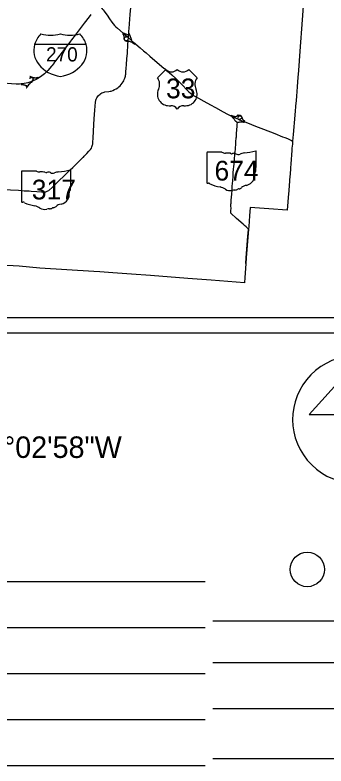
# Model space of a CAD drawing. Extents: x 0 to 34, y 0 to 22.
# Drawn here: x 6.458 to 8.488, y 11.177 to 16.072 of the extents above; entities that cross this region are included whole.
import ezdxf

# ---------------------------------------------------------------- set-up
doc = ezdxf.new("R2010")
doc.units = 0
for name, color, linetype in [('GM_X_County', 7, 'Continuous'), ('GM_X_Interchange_Ramps', 7, 'Continuous'), ('GM_X_Interstate_Route', 7, 'Continuous'), ('GM_X_Interstate_Shield', 7, 'Continuous'), ('GM_X_State_Route', 7, 'Continuous'), ('GM_X_State_Shield', 7, 'Continuous'), ('GM_X_US_Route', 7, 'Continuous'), ('GM_X_US_Shield', 7, 'Continuous'), ('SH_Data', 7, 'Continuous'), ('SH_Text', 7, 'Continuous')]:
    doc.layers.add(name, color=color, linetype=linetype)

msp = doc.modelspace()

# ---------------------------------------------------------------- linework, layer by layer
at = {"layer": 'GM_X_County'}
msp.add_lwpolyline([(8.3489, 16.2792), (8.3313, 16.0413), (8.3161, 15.8364), (8.3076, 15.7102), (8.3077, 15.7078), (8.3044, 15.666), (8.2999, 15.6045), (8.2955, 15.5437), (8.2932, 15.5151), (8.2922, 15.5061), (8.2906, 15.5018), (8.2836, 15.418), (8.2734, 15.2932), (8.2696, 15.2487), (8.2685, 15.2309), (8.267, 15.2168), (8.2657, 15.2028), (8.265, 15.1893), (8.2573, 15.1017), (8.2563, 15.0765), (8.2566, 15.0746), (8.2563, 15.0706), (8.2557, 15.0641), (8.2515, 15.0144), (8.2503, 14.9991), (8.2491, 14.9836), (8.2476, 14.9659), (8.2441, 14.9236), (8.2433, 14.9088), (8.2333, 14.7993), (8.1147, 14.8086), (7.9925, 14.8176), (7.9882, 14.7624), (7.983, 14.6937), (7.9818, 14.6762), (7.9675, 14.4885), (7.9649, 14.4509), (7.9575, 14.3612), (7.9551, 14.3263), (7.7391, 14.3437), (7.5857, 14.3553), (7.3417, 14.3728), (7.219, 14.3818), (7.0969, 14.3902), (7.0112, 14.3967), (6.9733, 14.3992), (6.6207, 14.4227), (6.4853, 14.4341), (6.2434, 14.4473)], dxfattribs=at)
at = {"layer": 'GM_X_Interchange_Ramps'}
for points in [[(7.1631, 15.9534), (7.1604, 15.9504), (7.1623, 15.9478), (7.1634, 15.9461), (7.1644, 15.9441), (7.1651, 15.9426), (7.1658, 15.9409), (7.1665, 15.939), (7.167, 15.9372), (7.1675, 15.9348), (7.1678, 15.9323), (7.1695, 15.9155), (7.1701, 15.9132), (7.1708, 15.9115), (7.1716, 15.9101), (7.1728, 15.9084), (7.1743, 15.9068), (7.1755, 15.9058), (7.177, 15.9047), (7.1785, 15.9039), (7.1798, 15.9034), (7.1816, 15.9028), (7.1832, 15.9026), (7.1854, 15.9022), (7.1942, 15.9014), (7.1961, 15.9012)], [(7.1989, 15.9399), (7.1975, 15.94), (7.1724, 15.9516), (7.1673, 15.9545), (7.1649, 15.9518)], [(7.1967, 15.9088), (7.1942, 15.909), (7.1933, 15.9077), (7.1921, 15.9065), (7.1909, 15.9056), (7.1896, 15.9049), (7.1884, 15.9043), (7.1872, 15.904), (7.1855, 15.9037), (7.1839, 15.9036), (7.1823, 15.9038), (7.1806, 15.9043), (7.1779, 15.9058), (7.176, 15.9071), (7.1744, 15.9086), (7.173, 15.9104), (7.1721, 15.9119), (7.1715, 15.9133), (7.1709, 15.9153), (7.1706, 15.9174), (7.1706, 15.9195), (7.171, 15.9218), (7.1716, 15.9232), (7.1722, 15.9244), (7.1731, 15.9255), (7.1745, 15.9269), (7.1759, 15.9279), (7.1775, 15.9287), (7.1791, 15.9291), (7.1807, 15.9293), (7.1825, 15.9293), (7.1839, 15.929), (7.1851, 15.9286), (7.1867, 15.9279), (7.1895, 15.9308)], [(7.209, 15.9367), (7.2084, 15.9365), (7.2076, 15.9374), (7.2065, 15.9382), (7.2054, 15.9389), (7.2041, 15.9394), (7.2028, 15.9397), (7.202, 15.9398), (7.2011, 15.9398), (7.1989, 15.9399)], [(7.2189, 15.9056), (7.2212, 15.9081), (7.2192, 15.9118), (7.209, 15.9367), (7.2032, 15.9507), (7.2021, 15.9536), (7.1998, 15.9538)], [(7.1961, 15.9012), (7.1977, 15.9011), (7.2023, 15.9008), (7.2038, 15.9006), (7.2056, 15.9003), (7.2105, 15.8992), (7.2144, 15.898), (7.2179, 15.8964), (7.221, 15.8949), (7.2241, 15.893), (7.2401, 15.8823), (7.2427, 15.8852)], [(6.5516, 15.6598), (6.5547, 15.6587), (6.5561, 15.6607), (6.5574, 15.6622), (6.5586, 15.6632), (6.5598, 15.664), (6.5619, 15.665), (6.5639, 15.6655), (6.5657, 15.6656), (6.568, 15.6652), (6.5694, 15.6648), (6.5716, 15.6636), (6.5729, 15.6624), (6.5739, 15.6611), (6.5746, 15.6598), (6.5751, 15.6584), (6.5755, 15.6566), (6.5756, 15.6548), (6.5753, 15.6527), (6.5747, 15.6508), (6.574, 15.6493), (6.5726, 15.6478), (6.5714, 15.6467), (6.5701, 15.6457), (6.572, 15.6408)], [(6.5552, 15.6698), (6.5568, 15.6692), (6.5639, 15.6669), (6.5639, 15.6655)], [(6.6107, 15.6604), (6.6079, 15.6647), (6.6061, 15.6638), (6.6043, 15.6631), (6.6023, 15.6624), (6.6004, 15.6619), (6.5984, 15.6614), (6.5968, 15.6611), (6.5946, 15.6609), (6.5923, 15.6608), (6.5901, 15.6609), (6.5876, 15.6611), (6.5854, 15.6614), (6.5831, 15.6619), (6.5803, 15.6628), (6.5679, 15.6668), (6.5571, 15.6703), (6.5556, 15.6708)], [(6.4976, 15.6224), (6.4979, 15.6188), (6.505, 15.6185), (6.5067, 15.6184), (6.5086, 15.6182), (6.5103, 15.618), (6.5118, 15.6178), (6.5135, 15.6175), (6.5149, 15.6171), (6.5166, 15.6167), (6.5188, 15.6161), (6.5209, 15.6154), (6.5228, 15.6148), (6.5254, 15.6135), (6.5263, 15.6131), (6.5272, 15.6125), (6.5279, 15.6118), (6.5284, 15.6113), (6.529, 15.6104), (6.5295, 15.6094), (6.53, 15.6085), (6.5334, 15.6071)], [(6.5303, 15.5979), (6.5334, 15.5967), (6.5348, 15.599), (6.5365, 15.6015), (6.5397, 15.6057), (6.5435, 15.61), (6.5508, 15.6208), (6.5519, 15.622), (6.5533, 15.6235), (6.5547, 15.625), (6.5561, 15.6262), (6.5577, 15.6276), (6.5591, 15.6288), (6.5605, 15.6298), (6.5622, 15.6311), (6.5654, 15.6332), (6.5668, 15.6341), (6.5685, 15.635), (6.5704, 15.6359), (6.569, 15.6395)], [(6.5254, 15.6135), (6.5255, 15.6138), (6.5318, 15.6118), (6.5346, 15.6103)], [(6.5346, 15.6103), (6.5363, 15.6098), (6.538, 15.6094), (6.5392, 15.6094), (6.5405, 15.6096), (6.5418, 15.61), (6.543, 15.6106), (6.5435, 15.61)], [(7.9137, 15.4195), (7.9109, 15.4196), (7.9099, 15.4169), (7.9092, 15.4154), (7.9083, 15.4141), (7.9073, 15.4129), (7.9061, 15.4118), (7.9049, 15.4109), (7.9034, 15.4102), (7.9017, 15.4095), (7.9002, 15.4092), (7.8989, 15.409), (7.8974, 15.409), (7.8957, 15.4092), (7.8902, 15.4106), (7.8752, 15.4153), (7.8692, 15.4175), (7.8674, 15.4137)], [(7.8759, 15.4095), (7.8744, 15.4062), (7.8757, 15.4052), (7.8776, 15.4036), (7.8794, 15.402), (7.8816, 15.3999), (7.8837, 15.3975), (7.8855, 15.3953), (7.8873, 15.3928), (7.8926, 15.3853), (7.8937, 15.3837), (7.8951, 15.3819), (7.8966, 15.3803), (7.8984, 15.3788), (7.9005, 15.3772), (7.9023, 15.3758), (7.904, 15.3747), (7.9055, 15.3739), (7.9069, 15.3731), (7.91, 15.3725)], [(7.9126, 15.4046), (7.9146, 15.4045), (7.9154, 15.4065), (7.9161, 15.4079), (7.9171, 15.4096), (7.9183, 15.4112), (7.9194, 15.4123), (7.9211, 15.4136), (7.923, 15.4145), (7.9251, 15.415), (7.9273, 15.4151), (7.9293, 15.4148), (7.931, 15.4143), (7.9326, 15.4135), (7.9338, 15.4126), (7.9351, 15.4113), (7.936, 15.41), (7.9367, 15.4088), (7.9374, 15.407), (7.9377, 15.4052), (7.9377, 15.4035), (7.9375, 15.4019), (7.9371, 15.4003), (7.9364, 15.3988), (7.9355, 15.3975), (7.9345, 15.3963), (7.9331, 15.3951), (7.9315, 15.3942), (7.9299, 15.3936), (7.9283, 15.3932), (7.9258, 15.3932), (7.9246, 15.3934), (7.9229, 15.3895)], [(7.9562, 15.3763), (7.9579, 15.3801), (7.9557, 15.3814), (7.954, 15.3826), (7.9524, 15.3839), (7.951, 15.3851), (7.9494, 15.3867), (7.9479, 15.3884), (7.9468, 15.3897), (7.9458, 15.3912), (7.9448, 15.3927), (7.9438, 15.3946), (7.9431, 15.3961), (7.9424, 15.3975), (7.938, 15.4087), (7.9371, 15.4104), (7.9359, 15.4121), (7.9347, 15.4132), (7.9332, 15.4144), (7.9319, 15.4151), (7.9306, 15.4156), (7.9288, 15.4161), (7.9263, 15.4166), (7.9147, 15.4173), (7.9135, 15.4174)]]:
    msp.add_lwpolyline(points, dxfattribs=at)
at = {"layer": 'GM_X_Interstate_Route'}
for points in [[(6.9528, 16.0757), (6.9417, 16.0606), (6.9095, 16.0189), (6.8837, 15.9844), (6.8496, 15.9407), (6.8266, 15.9101)], [(6.8266, 15.9101), (6.8195, 15.9005), (6.8194, 15.9004)], [(6.8194, 15.9004), (6.8149, 15.8944), (6.8008, 15.8755), (6.7659, 15.8307), (6.742, 15.7998), (6.718, 15.7674), (6.7139, 15.7619), (6.713, 15.7607)], [(6.6984, 15.7416), (6.6965, 15.7391), (6.6717, 15.71), (6.6583, 15.6964), (6.6503, 15.6887), (6.6498, 15.6883)], [(6.713, 15.7607), (6.6995, 15.743), (6.6984, 15.7416)], [(6.6498, 15.6883), (6.6419, 15.6814), (6.6324, 15.6745), (6.6107, 15.6604), (6.597, 15.6523), (6.5813, 15.645), (6.572, 15.6408), (6.569, 15.6395), (6.5659, 15.6383), (6.5649, 15.6378)], [(6.5413, 15.6307), (6.5297, 15.6277), (6.5167, 15.625), (6.4976, 15.6224), (6.4868, 15.6217), (6.4651, 15.6214), (6.4359, 15.6236), (6.3233, 15.6313), (6.3166, 15.6316), (6.3142, 15.6318)], [(6.5649, 15.6378), (6.5645, 15.6377), (6.5536, 15.6338), (6.5413, 15.6307)]]:
    msp.add_lwpolyline(points, dxfattribs=at)
at = {"layer": 'GM_X_Interstate_Shield'}
msp.add_line((6.9217, 15.8805), (6.5861, 15.8805), dxfattribs=at)
msp.add_line((6.9217, 15.8805), (6.5861, 15.8805), dxfattribs=at)
for centre, start_param, end_param in [((6.7973, 15.8408), 2.47259, 2.911027), ((6.6905, 16.1144), 4.415841, 5.008937), ((6.8173, 16.1144), 4.415841, 5.008937), ((6.7105, 15.8408), 0.230566, 0.669003), ((6.7973, 15.8408), 2.911027, 4.511031), ((6.7105, 15.8408), 4.913747, 6.513751)]:
    msp.add_ellipse(centre, major_axis=(0.2169, 0), ratio=0.8, start_param=start_param, end_param=end_param, dxfattribs=at)
at = {"layer": 'GM_X_State_Route'}
for points in [[(7.2009, 15.9663), (7.2026, 15.9848), (7.2096, 16.0757), (7.2115, 16.0987), (7.2129, 16.1182)], [(7.1978, 15.9235), (7.1989, 15.9399), (7.1998, 15.9538), (7.2004, 15.9613)], [(7.2004, 15.9613), (7.2009, 15.9663)], [(7.1963, 15.9037), (7.1967, 15.9088), (7.1978, 15.9235)], [(6.9856, 15.5173), (6.9876, 15.5239), (6.9909, 15.531), (6.9963, 15.5395), (7.0032, 15.5481), (7.0128, 15.5564), (7.0178, 15.5597), (7.0249, 15.5636), (7.034, 15.5676), (7.0391, 15.5693), (7.0446, 15.5704), (7.0695, 15.5733), (7.0782, 15.575), (7.0849, 15.5765), (7.0973, 15.5806), (7.1081, 15.5854), (7.1185, 15.5911), (7.1282, 15.5978), (7.1348, 15.6029), (7.1434, 15.6109), (7.1503, 15.6189), (7.158, 15.6285), (7.1643, 15.6371), (7.1677, 15.6437), (7.1713, 15.6515), (7.1745, 15.6593), (7.1783, 15.6729), (7.1797, 15.6793), (7.1803, 15.6859), (7.1818, 15.7004), (7.1838, 15.7254), (7.1853, 15.748), (7.1886, 15.7878), (7.191, 15.8206), (7.1948, 15.8823)], [(7.1948, 15.8823), (7.1961, 15.9012), (7.1963, 15.9037)], [(6.9723, 15.3582), (6.9748, 15.3951), (6.9787, 15.452), (6.9827, 15.504), (6.9849, 15.5148), (6.9856, 15.5173)], [(7.9088, 15.3558), (7.91, 15.3725)], [(7.91, 15.3725), (7.9149, 15.3732), (7.9201, 15.3741), (7.9247, 15.375), (7.9274, 15.3754), (7.9297, 15.3757), (7.9328, 15.3759), (7.9364, 15.3759), (7.9401, 15.3757), (7.9433, 15.3755), (7.947, 15.375), (7.9502, 15.3744), (7.9529, 15.3744), (7.9585, 15.3754)], [(6.9705, 15.3217), (6.9708, 15.3267), (6.9713, 15.3427), (6.9723, 15.3582)], [(7.9024, 15.2757), (7.9044, 15.3), (7.9062, 15.3225), (7.9081, 15.3469), (7.9088, 15.3558)], [(6.9089, 15.1513), (6.9268, 15.1693), (6.9404, 15.1833), (6.9498, 15.1942), (6.9562, 15.2046), (6.9595, 15.2129), (6.9637, 15.2251), (6.9649, 15.2303), (6.9661, 15.2396), (6.9683, 15.2738), (6.9697, 15.3097), (6.9704, 15.3206), (6.9705, 15.3217)], [(7.8952, 15.1847), (7.8961, 15.1921), (7.8974, 15.2109), (7.8984, 15.2229), (7.8997, 15.2428), (7.9021, 15.2727), (7.9024, 15.2757)], [(7.8927, 15.158), (7.8934, 15.1653), (7.8952, 15.1847)], [(6.6334, 14.919), (6.6464, 14.9186), (6.6525, 14.9192), (6.6582, 14.9202), (6.6628, 14.9215), (6.6674, 14.9229), (6.6729, 14.9253), (6.6781, 14.9282), (6.7021, 14.9488), (6.7421, 14.9883), (6.7806, 15.0266), (6.8182, 15.0629), (6.8344, 15.078), (6.8552, 15.0984), (6.8875, 15.13), (6.9002, 15.1425)], [(6.9002, 15.1425), (6.9038, 15.1461), (6.9089, 15.1513)], [(7.8675, 14.8253), (7.8674, 14.8273), (7.8674, 14.8359), (7.8675, 14.84), (7.8677, 14.8433), (7.8679, 14.8471), (7.8685, 14.8535), (7.8694, 14.8623), (7.8713, 14.8865), (7.8723, 14.9014), (7.8747, 14.9325), (7.8762, 14.9569), (7.8785, 14.9917), (7.8808, 15.0221), (7.8824, 15.0402), (7.8846, 15.0695), (7.8859, 15.0832), (7.8875, 15.1009), (7.8903, 15.1312), (7.8907, 15.1371), (7.8927, 15.158)], [(6.4018, 14.9349), (6.4291, 14.9332), (6.4815, 14.9296), (6.4817, 14.9296)], [(6.4817, 14.9296), (6.5186, 14.9267), (6.5326, 14.9257), (6.5352, 14.9256)], [(6.5352, 14.9256), (6.5495, 14.925), (6.5623, 14.9239), (6.5636, 14.9238)], [(6.5636, 14.9238), (6.6, 14.9215), (6.6311, 14.9191), (6.6334, 14.919)], [(7.8656, 14.7791), (7.8656, 14.7791), (7.8669, 14.7937)], [(7.8669, 14.7937), (7.867, 14.7938), (7.8674, 14.8006), (7.8677, 14.8074), (7.8678, 14.813), (7.8675, 14.8253)], [(7.9818, 14.6762), (7.9669, 14.6906), (7.9565, 14.7001), (7.9482, 14.7072), (7.9476, 14.7077), (7.9039, 14.7455), (7.8656, 14.7791)], [(7.9782, 14.6293), (7.9814, 14.6713)], [(7.9814, 14.6713), (7.9818, 14.6762)], [(7.965, 14.4522), (7.9675, 14.4885), (7.9782, 14.6293)]]:
    msp.add_lwpolyline(points, dxfattribs=at)
at = {"layer": 'GM_X_State_Shield'}
for p, q in [((7.8083, 15.1777), (7.714, 15.1777)), ((8.0329, 15.0803), (8.0329, 15.1826)), ((7.7108, 15.1744), (7.7108, 14.9788)), ((8.0329, 15.0803), (8.0329, 15.0803)), ((6.5001, 15.0514), (6.5001, 14.8558)), ((6.5976, 15.0548), (6.5033, 15.0548)), ((6.8222, 14.9573), (6.8222, 15.0596)), ((6.8222, 14.9573), (6.8222, 14.9573))]:
    msp.add_line(p, q, dxfattribs=at)
for centre, major_axis, start_param, end_param in [((7.7145, 15.1748), (0.00373, 0), 1.712693, 3.28349), ((7.8308, 15.2004), (0.0362, 0), 4.042523, 4.731795), ((7.9182, 15.4444), (0.3416, 0), 4.814394, 5.042369), ((8.0293, 15.183), (0.00359, 0), 6.141152, 7.989035), ((7.8428, 15.0679), (0.1299, 0), 1.404758, 1.657858), ((7.8723, 15.1758), (0.0104, 0), 3.836095, 5.185415), ((7.8876, 15.1532), (0.0217, 0), 0.950623, 2.079405), ((7.9156, 15.1842), (0.0261, 0), 4.081561, 5.145723), ((7.9617, 15.118), (0.0687, 0), 1.699011, 2.107814), ((8.0291, 15.0799), (0.00384, 0), 5.05454, 6.418171), ((6.5038, 15.0518), (0.00373, 0), 1.712693, 3.28349), ((6.6201, 15.0775), (0.0362, 0), 4.042523, 4.731795), ((6.6321, 14.945), (0.1299, 0), 1.404758, 1.657858), ((6.6616, 15.0528), (0.0104, 0), 3.836095, 5.185415), ((6.6769, 15.0302), (0.0217, 0), 0.950623, 2.079405), ((6.7049, 15.0612), (0.0261, 0), 4.081561, 5.145723), ((6.751, 14.995), (0.0687, 0), 1.699011, 2.107814), ((6.7075, 15.3214), (0.3416, 0), 4.814394, 5.042369), ((6.8186, 15.06), (0.00359, 0), 6.141152, 7.989035), ((7.9373, 15.0244), (0.0854, 0), 5.101752, 6.440018), ((8.0457, 15.0375), (0.0242, 0), 2.387724, 3.262537), ((8.0321, 15.0728), (0.00555, 0), 1.883978, 3.671073), ((7.9968, 15.0598), (0.0333, 0), 5.934695, 6.695948), ((6.8214, 14.9498), (0.00555, 0), 1.883978, 3.671073), ((6.7861, 14.9368), (0.0333, 0), 5.934695, 6.695948), ((6.8184, 14.9569), (0.00384, 0), 5.05454, 6.418171), ((7.7145, 14.9784), (0.00376, 0), 3.00124, 4.508301), ((7.7151, 14.9984), (0.0287, 0), 4.665946, 4.897461), ((7.721, 14.9675), (0.0104, 0), 0.519207, 1.627899), ((7.8517, 15.1432), (0.2467, 0), 4.195997, 4.488961), ((7.7782, 14.8909), (0.0772, 0), 0.823519, 1.323587), ((7.8617, 14.9665), (0.049, 0), 4.026481, 4.996735), ((7.89, 14.8989), (0.0402, 0), 1.495662, 1.94098), ((7.8936, 14.9519), (0.0261, 0), 4.691044, 5.507374), ((7.9172, 14.9329), (0.00735, 0), 1.147584, 2.315152), ((7.914, 14.9598), (0.0276, 0), 4.937069, 5.64225), ((7.9733, 14.9239), (0.0468, 0), 1.647645, 2.488434), ((6.7266, 14.9015), (0.0854, 0), 5.101752, 6.440018), ((6.8351, 14.9145), (0.0242, 0), 2.387724, 3.262537), ((6.5038, 14.8554), (0.00376, 0), 3.00124, 4.508301), ((6.5044, 14.8754), (0.0287, 0), 4.665946, 4.897461), ((6.5103, 14.8445), (0.0104, 0), 0.519207, 1.627899), ((6.6411, 15.0202), (0.2467, 0), 4.195997, 4.488961), ((6.7626, 14.8009), (0.0468, 0), 1.647645, 2.488434), ((6.5675, 14.7679), (0.0772, 0), 0.823519, 1.323587), ((6.651, 14.8436), (0.049, 0), 4.026481, 4.996735), ((6.6793, 14.7759), (0.0402, 0), 1.495662, 1.94098), ((6.6829, 14.8289), (0.0261, 0), 4.691044, 5.507374), ((6.7065, 14.81), (0.00735, 0), 1.147584, 2.315152), ((6.7033, 14.8369), (0.0276, 0), 4.937069, 5.64225)]:
    msp.add_ellipse(centre, major_axis=major_axis, ratio=0.8, start_param=start_param, end_param=end_param, dxfattribs=at)
at = {"layer": 'GM_X_US_Route'}
for points in [[(6.9959, 16.1396), (6.9998, 16.1371), (7.0017, 16.1357), (7.0072, 16.1313), (7.0149, 16.1248), (7.0213, 16.1187), (7.0271, 16.1126), (7.0331, 16.1061), (7.0397, 16.0975), (7.0449, 16.0905), (7.0587, 16.0702), (7.0742, 16.0473), (7.0889, 16.026), (7.0978, 16.0148), (7.1073, 16.0038), (7.1154, 15.9953), (7.1257, 15.9854), (7.1631, 15.9534), (7.1649, 15.9518), (7.1895, 15.9308), (7.1978, 15.9235)], [(7.1978, 15.9235), (7.2189, 15.9056), (7.2252, 15.9002)], [(7.2252, 15.9002), (7.2427, 15.8852), (7.2464, 15.882)], [(7.2464, 15.882), (7.2755, 15.8573), (7.2975, 15.8384), (7.3135, 15.8246)], [(7.3135, 15.8246), (7.3375, 15.8042), (7.3857, 15.7629), (7.4283, 15.7264), (7.4331, 15.7221), (7.4382, 15.7177), (7.4639, 15.6962), (7.4804, 15.682), (7.5078, 15.6577), (7.5198, 15.6457), (7.5305, 15.6349), (7.5547, 15.6095), (7.5752, 15.5876), (7.5918, 15.5716), (7.6037, 15.5619), (7.6131, 15.5547), (7.6235, 15.5476), (7.636, 15.5399), (7.7105, 15.4992), (7.7895, 15.4558), (7.7919, 15.4545)], [(7.7919, 15.4545), (7.8454, 15.4252), (7.8674, 15.4137), (7.8759, 15.4095), (7.8885, 15.4036), (7.9119, 15.394)], [(7.9119, 15.394), (7.9156, 15.3925)], [(7.9156, 15.3925), (7.9229, 15.3895), (7.9562, 15.3763), (7.9585, 15.3754)], [(7.9585, 15.3754), (7.9852, 15.3651), (8.0173, 15.3523), (8.0344, 15.3456), (8.0345, 15.3456)], [(8.0345, 15.3456), (8.0391, 15.3438)], [(8.0391, 15.3438), (8.0458, 15.3413), (8.0797, 15.3277), (8.154, 15.2985), (8.2047, 15.2784), (8.2185, 15.273), (8.2354, 15.2664), (8.246, 15.2615), (8.2617, 15.2533), (8.2696, 15.2487)]]:
    msp.add_lwpolyline(points, dxfattribs=at)
at = {"layer": 'GM_X_US_Shield'}
for p, q in [((7.4418, 15.7167), (7.3881, 15.663)), ((7.6458, 15.663), (7.5921, 15.7167)), ((7.4632, 15.4805), (7.474, 15.4805)), ((7.5599, 15.4805), (7.5706, 15.4805))]:
    msp.add_line(p, q, dxfattribs=at)
for centre, radius, start, end in [((7.4793, 15.7551), 0.0537, 225.573, 314.427), ((7.5545, 15.7551), 0.0537, 225.573, 314.427), ((7.3265, 15.6199), 0.0752, 334.5471, 35.0009), ((7.7073, 15.6199), 0.0752, 144.9991, 205.4529), ((7.4624, 15.5556), 0.0752, 154.8319, 270.6383), ((7.5715, 15.5556), 0.0752, 269.3617, 25.1681), ((7.474, 15.4268), 0.0537, 36.8699, 90), ((7.5599, 15.4268), 0.0537, 90, 143.1301)]:
    msp.add_arc(centre, radius, start, end, dxfattribs=at)
at = {"layer": 'SH_Data'}
for p, q in [((2.1, 14.1), (8.9, 14.1)), ((2, 14), (9, 14)), ((8.6845, 13.8091), (8.3769, 13.4678)), ((8.3769, 13.4678), (8.9921, 13.4678)), ((7.7, 12.3767), (4.4937, 12.3767)), ((9, 12.1207), (7.75, 12.1207)), ((7.7, 12.0767), (3.9895, 12.0767)), ((9, 11.8491), (7.75, 11.8491)), ((7.7, 11.7767), (3.6192, 11.7767)), ((9, 11.5491), (7.75, 11.5491)), ((7.7, 11.4767), (3.3288, 11.4767)), ((9, 11.2223), (7.75, 11.2223)), ((7.7, 11.1767), (4.7452, 11.1767))]:
    msp.add_line(p, q, dxfattribs=at)
msp.add_circle((8.3654, 12.4575), 0.1121, dxfattribs=at)
msp.add_arc((8.6845, 13.4353), 0.4148, 129.7798, 129.7633, dxfattribs=at)

# ---------------------------------------------------------------- texts
at = {"layer": 'GM_X_Interstate_Shield'}
msp.add_text('270', height=0.09255, dxfattribs=at).set_placement((6.6605, 15.7691))
at = {"layer": 'GM_X_State_Shield'}
for s, p in [('674', (7.76, 14.9926)), ('317', (6.5676, 14.8696))]:
    msp.add_text(s, height=0.12885, dxfattribs=at).set_placement(p)
at = {"layer": 'GM_X_US_Shield'}
msp.add_text('33', height=0.12885, dxfattribs=at).set_placement((7.4436, 15.5288))
at = {"layer": 'SH_Text'}
msp.add_text('LATITUDE:  40°17\'52"N  LONGITUDE:  83°02\'58"W  ', height=0.14, dxfattribs=at).set_placement((2.8259, 13.1847))

doc.saveas('drawing.dxf')
